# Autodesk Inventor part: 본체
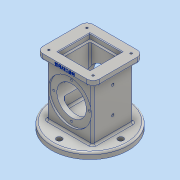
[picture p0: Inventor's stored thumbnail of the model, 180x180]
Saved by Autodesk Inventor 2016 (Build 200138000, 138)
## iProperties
Created: 2018-10
Part Number: 본체
Material: 알루미늄 6061
Document SubType Name: Modeling
Designer: 3sil_cad018
Density: 2.7 g/cm^3
Appearance: 알루미늄 - 평지
Mass: 984.575 g
Surface Area: 743.905 cm^2
Volume: 364.657 cm^3
Author: 3sil_cad018
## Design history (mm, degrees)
sketch "스케치2"
  geometry: C1 r 62.5 at (0, 0); 1 further point
  constraints: 1 centre point, 1 coincident
  dimensions: "d2" = 125 diameter of C1
extrude "돌출1" new body sketch "스케치2" distance "d3" = 10; taper "d4" = 0 deg
sketch "스케치3" dims "d5" = 100
  geometry: 3 further points
  constraints: 2 horizontal alignment, 1 coincident, 2 other
hole "구멍1" sketch "스케치3" at (50, 0) diameter "d6" = 9; stored, may be unused: countersink angle "d10" = 90 deg, drill point angle "d12" = 118 deg; dims "d7" = 6, "d8" = 4, "d9" = 2, "d11" = 8
sketch "스케치4"
  geometry: L1 (37, -33)-(-37, -33); L2 (-37, -33)-(-37, 33); L3 (-37, 33)-(37, 33); L4 (37, 33)-(37, -33); 3 further points
  constraints: 8 end point, 2 midpoint, 2 parallel, 1 horizontal, 1 horizontal alignment, 1 perpendicular, 1 vertical alignment
  dimensions: "d16" = 74 distance of L1.start L1.end; "d17" = 66 distance of L1.end L2.end
extrude "돌출2" join sketch "스케치4" distance "d18" = 88; taper "d19" = 0 deg
sketch "스케치5"
  geometry: L1 (46, -41)-(-46, -41); L2 (-46, -41)-(-46, 41); L3 (-46, 41)-(46, 41); L4 (46, 41)-(46, -41); 3 further points
  constraints: 8 end point, 2 midpoint, 2 parallel, 1 horizontal, 1 horizontal alignment, 1 perpendicular, 1 vertical alignment
  dimensions: "d20" = 92 distance of L1.start L1.end; "d21" = 82 distance of L1.end L2.end
extrude "돌출3" join sketch "스케치5" distance "d22" = 10; taper "d23" = 0 deg
sketch "스케치6"
  geometry: L1 (-26, -26)-(26, -26); L2 (26, -26)-(26, 26); L3 (26, 26)-(-26, 26); L4 (-26, 26)-(-26, -26); 3 further points
  constraints: 8 end point, 2 midpoint, 2 parallel, 1 horizontal, 1 horizontal alignment, 1 perpendicular, 1 vertical alignment
  dimensions: "d24" = 52 distance of L1.start L1.end; "d25" = 52 distance of L1.end L2.end
extrude "돌출4" cut sketch "스케치6" distance "d26" = 8; taper "d27" = 0 deg
sketch "스케치7"
  geometry: L1 (22, -22)-(-22, -22); L2 (-22, -22)-(-22, 22); L3 (-22, 22)-(22, 22); L4 (22, 22)-(22, -22); 3 further points
  constraints: 8 end point, 2 midpoint, 2 parallel, 1 horizontal, 1 horizontal alignment, 1 perpendicular, 1 vertical alignment
  dimensions: "d28" = 44 distance of L1.start L1.end; "d29" = 44 distance of L1.end L2.end
extrude "돌출5" cut sketch "스케치7" distance "d30" = 74; taper "d31" = 0 deg
fillet "모깎기1" dims "d32" = 3
fillet "모깎기2" dims "d33" = 10
fillet "모깎기3" dims "d34" = 3
fillet "모깎기4" dims "d35" = 3
sketch "스케치8"
  geometry: L1 (-28.5, -10)-(96.5, -10) reference; L2 (-2, 98)-(70, 98) reference; C1 r 35 at (34, 44); 2 further points
  constraints: 1 centre point, 1 midpoint, 1 vertical alignment
  dimensions: "d36" = 54 distance from line of L1 C1.centre; "d37" = 70 diameter of C1
extrude "돌출6" cut sketch "스케치8" distance "d38" = 3; taper "d39" = 0 deg
hole "구멍2" diameter "d42" = 48; stored, may be unused: countersink angle "d46" = 90 deg, drill point angle "d48" = 118 deg; dims "d40" = 10, "d41" = 10, "d43" = 6, "d44" = 4, "d45" = 2, "d47" = 8
sketch "스케치9" dims "d49" = 58
  geometry: A1 r 35 centre (0, 0) between (34, 8.307) and (-34, 8.307) reference; 3 further points
  constraints: 2 vertical alignment, 1 coincident, 2 other
hole "구멍3" sketch "스케치9" at (0, 29) diameter "d50" = 3.242; stored, may be unused: countersink angle "d54" = 90 deg, drill point angle "d56" = 118 deg; dims "d51" = 4, "d52" = 4, "d53" = 2, "d55" = 6
fillet "모깎기5" dims "d60" = 3
chamfer "모따기1" distance "d61" = 1; stored, may be unused: second distance "d62" = 2, angle "d63" = 45 deg
sketch "스케치10"
  geometry: A1 r 10 centre (36, -31) between (36, -41) and (46, -31) reference; A2 r 10 centre (-36, -31) between (-46, -31) and (-36, -41) reference; A3 r 10 centre (-36, 31) between (-36, 41) and (-46, 31) reference; A4 r 10 centre (36, 31) between (46, 31) and (36, 41) reference; 1 further point
  dimensions: "d64" = 72 distance of A2.centre A1.centre (derived); "d65" = 62 distance of A4.centre A1.centre (derived)
hole "구멍4" sketch "스케치10" at (36, 31), (36, -31), (-36, -31), (-36, 31) diameter "d66" = 3.242; stored, may be unused: countersink angle "d70" = 90 deg, drill point angle "d72" = 118 deg; dims "d67" = 4, "d68" = 4, "d69" = 2, "d71" = 6
sketch "스케치11"
  geometry: L1 (-32.5, -95)-(92.5, -95) reference; 4 further points
  constraints: 2 vertical alignment, 1 midpoint
  dimensions: "d73" = 37 distance from line of L1 point (30, -58); "d75" = 43 distance of point (30, -58) point (30, -15)
hole "구멍5" sketch "스케치11" at (30, -15), (30, -58) diameter "d76" = 4.134; stored, may be unused: countersink angle "d80" = 90 deg, drill point angle "d82" = 118 deg; dims "d77" = 20, "d78" = 4, "d79" = 2, "d81" = 20
fillet "모깎기6" dims "d83" = 3
sketch "스케치12"
  geometry: L1 (0, 0)-(0, 28); L2 (0, 28)-(18, 24.826); L3 (18, 24.826)-(18, 0); L4 (18, 0)-(0, 0)
  constraints: 8 end point, 1 parallel, 1 perpendicular, 1 vertical
  dimensions: "d84" = 18 distance of L3.end L1.start; "d85" = 80 deg angle of L1 L2; "d86" = 28 distance of L1.start L1.end
revolve "회전1" sketch "스케치12" stored, may be unused: angle "d87" = 90 deg
fillet "모깎기7" dims "d88" = 3
sketch "스케치13"
  geometry: L1 (82, -7)-(82, 0) reference; L2 (-10, 0)-(-10, -7) reference; L3 (0, 0)-(72, 0) reference; 2 further points
  constraints: 1 other
  dimensions: "d89" = 46 distance from line of L1 point (36, -4); "d90" = 46 distance from line of L2 point (36, -4) (derived); "d91" = 4 distance from line of L3 point (36, -4)
feature "엠보싱1" sketch "스케치13" dims "d92" = 0.5, "d93" = 0
fillet "모깎기8" dims "d94" = 3
node "솔리드1"
pattern_circular "원형 패턴1" dims angle "d14" = 360 deg
mirror "대칭1"
pattern_circular "원형 패턴2" dims angle "d58" = 360 deg
mirror "대칭2"
